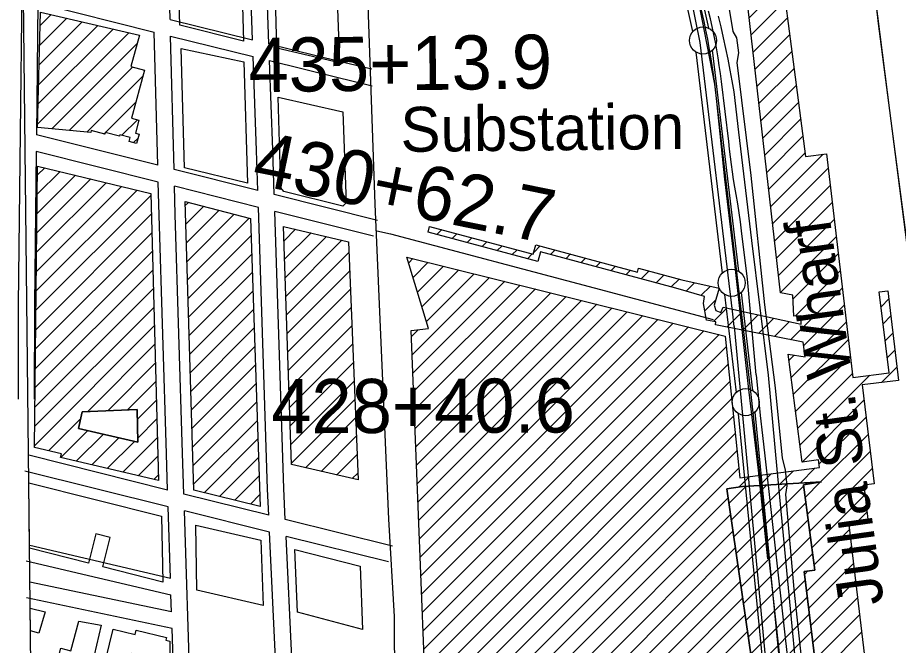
# Model space of a CAD drawing. Extents: x 3677843 to 3715951, y 511991 to 537744.
# Drawn here: x 3681974 to 3683602, y 526703 to 527864 of the extents above; entities that cross this region are included whole.
import ezdxf

# ---------------------------------------------------------------- set-up
doc = ezdxf.new("R2010")
doc.units = 0
for name, color, linetype in [('V-BLDG-IDEN', 7, 'Continuous'), ('V-BLDG-OTLN', 7, 'Continuous'), ('V-CHAN-DOCK', 7, 'Continuous'), ('V-FLOD-BASE', 7, 'Continuous'), ('V-GRID-FRAM', 7, 'Continuous'), ('V-RAIL-TRAK', 7, 'Continuous'), ('V-RIVR-EDGE', 7, 'Continuous'), ('V-RIVR-FERY', 7, 'Continuous'), ('V-ROAD-CNTR', 7, 'Continuous'), ('V-SITE-OTLN', 7, 'Continuous'), ('V-SITE-OTLN-IDEN', 7, 'Continuous'), ('V-SURV-IDEN', 7, 'Continuous'), ('V-SURV-LINE', 7, 'Continuous'), ('V-UTIL-LINE', 7, 'Continuous')]:
    doc.layers.add(name, color=color, linetype=linetype)

msp = doc.modelspace()

# ---------------------------------------------------------------- linework, layer by layer
at = {"layer": 'V-BLDG-OTLN'}
for p, q in [((3683326.4, 527863.3), (3683389.2, 527926.2)), ((3683330, 527831.6), (3683393.2, 527894.9)), ((3682015.7, 527848.9), (3682036.1, 527869.4)), ((3682013.6, 527776.1), (3682093.4, 527855.9)), ((3682014.6, 527812.5), (3682064.8, 527862.6)), ((3683333.6, 527799.8), (3683397.3, 527863.5)), ((3682011.5, 527703.4), (3682150.7, 527842.5)), ((3682012.6, 527739.7), (3682122, 527849.2)), ((3682010.5, 527667), (3682179.3, 527835.8)), ((3683337.2, 527768.1), (3683401.3, 527832.2)), ((3682037.1, 527658.2), (3682194.6, 527815.7)), ((3683340.8, 527736.3), (3683405.4, 527800.9)), ((3682069.4, 527655.2), (3682186.6, 527772.4)), ((3682101.8, 527652.2), (3682205.8, 527756.2)), ((3683344.4, 527704.6), (3683409.4, 527769.6)), ((3683348, 527672.8), (3683413.5, 527738.3)), ((3682136.3, 527651.4), (3682192.5, 527707.5)), ((3683351.6, 527641.1), (3683417.5, 527707)), ((3682166.4, 527646.1), (3682195.2, 527674.9)), ((3683355.2, 527609.3), (3683421.6, 527675.7)), ((3682133.5, 527648.6), (3682135.4, 527650.4)), ((3682188.2, 527632.5), (3682196.4, 527640.7)), ((3683358.8, 527577.6), (3683425.6, 527644.4)), ((3683362.4, 527545.8), (3683429.6, 527613.1)), ((3683366, 527514.1), (3683463, 527611)), ((3682010.2, 527537.1), (3682052.3, 527579.3)), ((3682010.6, 527572.9), (3682023.9, 527586.2)), ((3683369.7, 527482.3), (3683472.4, 527585.1)), ((3682009.4, 527465.6), (3682109.2, 527565.4)), ((3682009.8, 527501.4), (3682080.8, 527572.3)), ((3682008.2, 527358.4), (3682194.6, 527544.7)), ((3682008.6, 527394.1), (3682166.1, 527551.6)), ((3682009, 527429.9), (3682137.7, 527558.5)), ((3683373.3, 527450.6), (3683476.1, 527553.5)), ((3682007.8, 527322.6), (3682220.5, 527535.3)), ((3682283.9, 527516.1), (3682289.7, 527521.9)), ((3682284.9, 527481.8), (3682317.8, 527514.6)), ((3683376.9, 527418.9), (3683479.9, 527521.9)), ((3682007.4, 527286.8), (3682221.4, 527500.9)), ((3682286, 527447.4), (3682345.9, 527507.4)), ((3682287, 527413.1), (3682374, 527500.1)), ((3682288, 527378.8), (3682402.1, 527492.9)), ((3683380.5, 527387.1), (3683483.6, 527490.2)), ((3682007, 527251.1), (3682222.3, 527466.4)), ((3682466.4, 527451.1), (3682487.8, 527472.5)), ((3682467.5, 527416.9), (3682516.4, 527465.7)), ((3682749.1, 527462.9), (3682757.9, 527471.7)), ((3682777, 527455.4), (3682785.8, 527464.2)), ((3682289, 527344.4), (3682405.4, 527460.8)), ((3682468.7, 527382.6), (3682544.9, 527458.9)), ((3682469.8, 527348.4), (3682573.5, 527452.1)), ((3682804.9, 527447.9), (3682813.7, 527456.7)), ((3682832.8, 527440.4), (3682841.5, 527449.2)), ((3683384.1, 527355.4), (3683487.4, 527458.6)), ((3682006.6, 527215.3), (3682223.3, 527432)), ((3682470.9, 527314.2), (3682586.4, 527429.7)), ((3682860.6, 527432.9), (3682869.4, 527441.7)), ((3682888.5, 527425.5), (3682897.3, 527434.2)), ((3682928, 527429.6), (3682940, 527441.6)), ((3682959.3, 527425.5), (3682967.9, 527434.1)), ((3682290, 527310.1), (3682406.6, 527426.6)), ((3682696.9, 527410.6), (3682704.6, 527418.4)), ((3682916.4, 527418), (3682925.2, 527426.8)), ((3682987.2, 527418), (3682995.8, 527426.7)), ((3683015, 527410.6), (3683023.6, 527419.2)), ((3683407.7, 527343.6), (3683491.1, 527427)), ((3682006.2, 527179.6), (3682224.2, 527397.5)), ((3682705, 527383.4), (3682733, 527411.3)), ((3682713.2, 527356.2), (3682761.3, 527404.3)), ((3682721.3, 527329), (3682789.6, 527397.3)), ((3683042.9, 527403.1), (3683051.5, 527411.7)), ((3683070.8, 527395.6), (3683079.4, 527404.2)), ((3683098.6, 527388.1), (3683107.2, 527396.7)), ((3682291.1, 527275.8), (3682407.7, 527392.4)), ((3682472, 527280), (3682587.8, 527395.7)), ((3682703.2, 527240.2), (3682846.2, 527383.2)), ((3682729.5, 527301.8), (3682817.9, 527390.2)), ((3683126.5, 527380.6), (3683141, 527395.1)), ((3683154.4, 527373.1), (3683168.9, 527387.6)), ((3683182.3, 527365.7), (3683196.7, 527380.1)), ((3683411.2, 527311.8), (3683494.8, 527395.4)), ((3682704.6, 527206.2), (3682874.6, 527376.2)), ((3682705.9, 527172.2), (3682902.9, 527369.1)), ((3683209.8, 527357.8), (3683225.6, 527373.6)), ((3683237.2, 527349.9), (3683254.7, 527367.4)), ((3683403, 527268.2), (3683498.6, 527363.8)), ((3682005.8, 527143.8), (3682225.1, 527363.1)), ((3682292.1, 527241.4), (3682408.9, 527358.2)), ((3682473.2, 527245.7), (3682589.1, 527361.7)), ((3682707.3, 527138.2), (3682931.2, 527362.1)), ((3682708.6, 527104.1), (3682959.5, 527355.1)), ((3682710, 527070.1), (3682987.8, 527348)), ((3682711.3, 527036.1), (3683016.2, 527341)), ((3682712.6, 527002.1), (3683044.5, 527334)), ((3683244.6, 527321.9), (3683264.8, 527342.1)), ((3683427.1, 527257), (3683502.3, 527332.2)), ((3683570.2, 527329.3), (3683584.5, 527343.7)), ((3682005.4, 527108.1), (3682226, 527328.6)), ((3682293.1, 527207.1), (3682410.1, 527324)), ((3682474.3, 527211.5), (3682590.5, 527327.7)), ((3682714, 526968.1), (3683072.8, 527326.9)), ((3682715.3, 526934.1), (3683101.1, 527319.9)), ((3683260.2, 527302.2), (3683284.8, 527326.8)), ((3683284.8, 527291.4), (3683313.9, 527320.5)), ((3682716.7, 526900.1), (3683129.5, 527312.9)), ((3682718, 526866.1), (3683157.8, 527305.8)), ((3682719.3, 526832), (3683186.1, 527298.8)), ((3683314.4, 527285.6), (3683343, 527314.2)), ((3683343.9, 527279.8), (3683372.1, 527308)), ((3683373.5, 527274), (3683401.1, 527301.7)), ((3683403.9, 527198.4), (3683506, 527300.5)), ((3683574, 527297.8), (3683588.3, 527312.1)), ((3682005, 527072.3), (3682226.9, 527294.2)), ((3682294.1, 527172.8), (3682411.2, 527289.9)), ((3682475.4, 527177.3), (3682591.8, 527293.7)), ((3682701.9, 527274.2), (3682714.3, 527286.7)), ((3682720.7, 526798), (3683214.4, 527291.8)), ((3682722, 526764), (3683242.7, 527284.7)), ((3682723.4, 526730), (3683271.1, 527277.7)), ((3683408, 527167.1), (3683509.8, 527268.9)), ((3683577.8, 527266.2), (3683592.1, 527280.6)), ((3682103.7, 527135.6), (3682227.8, 527259.8)), ((3682295.1, 527138.4), (3682412.4, 527255.7)), ((3682476.5, 527143), (3682593.2, 527259.7)), ((3682724.7, 526696), (3683284.1, 527255.3)), ((3683399.9, 527229.7), (3683409.8, 527239.6)), ((3683412, 527135.8), (3683513.5, 527237.3)), ((3683581.6, 527234.7), (3683595.9, 527249)), ((3682140.4, 527137), (3682228.7, 527225.3)), ((3682296.2, 527104.1), (3682413.6, 527221.5)), ((3682477.7, 527108.8), (3682594.5, 527225.7)), ((3682726.1, 526662), (3683287.4, 527223.3)), ((3683571.3, 527189.1), (3683599.7, 527217.5)), ((3683416.1, 527104.5), (3683517.3, 527205.7)), ((3683420.1, 527073.2), (3683549.3, 527202.4)), ((3682177.2, 527138.4), (3682229.6, 527190.9)), ((3682297.2, 527069.8), (3682414.7, 527187.3)), ((3682478.8, 527074.6), (3682595.9, 527191.7)), ((3682727.4, 526628), (3683290.7, 527191.2)), ((3682195.3, 527121.2), (3682230.6, 527156.4)), ((3682298.2, 527035.4), (3682415.9, 527153.1)), ((3682479.9, 527040.3), (3682597.3, 527157.7)), ((3682728.7, 526593.9), (3683293.9, 527159.2)), ((3683424.2, 527042), (3683538.6, 527156.3)), ((3682030.9, 527062.8), (3682090.5, 527122.4)), ((3682195.8, 527086.3), (3682231.5, 527122)), ((3682506.3, 527031.4), (3682598.6, 527123.7)), ((3682730.1, 526559.9), (3683297.2, 527127.1)), ((3683455.5, 527037.9), (3683542.4, 527124.7)), ((3682299.2, 527001.1), (3682417.1, 527118.9)), ((3682053.6, 527050.2), (3682103.8, 527100.4)), ((3682082.2, 527043.4), (3682132.4, 527093.6)), ((3682168.1, 527023.3), (3682232.4, 527087.5)), ((3682535, 527024.7), (3682600, 527089.7)), ((3682731.4, 526525.9), (3683300.5, 527095)), ((3683458.5, 527005.5), (3683546.2, 527093.2)), ((3682110.9, 527036.7), (3682161, 527086.9)), ((3682139.5, 527030), (3682189.7, 527080.2)), ((3682318.7, 526985.3), (3682418.2, 527084.7)), ((3682563.7, 527018.1), (3682601.3, 527055.7)), ((3682732.8, 526491.9), (3683303.8, 527063)), ((3683434, 526945.7), (3683550, 527061.6)), ((3682196.8, 527016.6), (3682233.3, 527053.1)), ((3682347.2, 526978.3), (3682419.4, 527050.5)), ((3682734.1, 526457.9), (3683307.1, 527030.9)), ((3683383.3, 527001.1), (3683408.1, 527025.8)), ((3683420.9, 527003.3), (3683448.7, 527031.1)), ((3683438.3, 526914.6), (3683553.8, 527030.1)), ((3682225.4, 527009.9), (3682234.2, 527018.7)), ((3682375.6, 526971.4), (3682420.6, 527016.4)), ((3682592.4, 527011.4), (3682602.7, 527021.7)), ((3683307.6, 526996), (3683326.9, 527015.3)), ((3683345.7, 526998.8), (3683367.5, 527020.6)), ((3681995.8, 526883), (3681994.5, 527003.6)), ((3681994.5, 527003.6), (3682239.7, 526942.2)), ((3683288.8, 526965.4), (3683320.8, 526997.3)), ((3683293.3, 526934.5), (3683358.4, 526999.6)), ((3683297.8, 526903.7), (3683396, 527001.8)), ((3683302.3, 526872.8), (3683427, 526997.5)), ((3683429.8, 526976.8), (3683458.3, 527005.3)), ((3683430, 527000.5), (3683433.5, 527004)), ((3682404.1, 526964.5), (3682421.7, 526982.2)), ((3682735.4, 526423.9), (3683287.3, 526975.7)), ((3683442.5, 526883.4), (3683540.3, 526981.2)), ((3683306.8, 526842), (3683431.2, 526966.4)), ((3682239.7, 526942.2), (3682242.1, 526820.3)), ((3682736.8, 526389.9), (3683291.8, 526944.9)), ((3683521.9, 526927.5), (3683544.1, 526949.7)), ((3683311.3, 526811.1), (3683435.5, 526935.2)), ((3682118.5, 526909.5), (3682104.9, 526855.4)), ((3682144.9, 526902.8), (3682118.5, 526909.5)), ((3682738.1, 526355.8), (3683296.3, 526914)), ((3683446.7, 526852.3), (3683511.9, 526917.5)), ((3682131.1, 526848.4), (3682144.9, 526902.8)), ((3683315.8, 526780.3), (3683439.7, 526904.1)), ((3682104.9, 526855.4), (3681995.8, 526883)), ((3682739.5, 526321.8), (3683300.8, 526883.2)), ((3683432.4, 526802.7), (3683515.6, 526885.9)), ((3683320.3, 526749.4), (3683443.9, 526873)), ((3682242.1, 526820.3), (3682131.1, 526848.4)), ((3682740.8, 526287.8), (3683305.3, 526852.3)), ((3683436.3, 526771.2), (3683519.4, 526854.3)), ((3683428.5, 526834.1), (3683435.1, 526840.7)), ((3682742.2, 526253.8), (3683309.8, 526821.5)), ((3683324.8, 526718.6), (3683429.8, 526823.6)), ((3683440.2, 526739.7), (3683523.1, 526822.6)), ((3682743.5, 526219.8), (3683314.3, 526790.6)), ((3683329.4, 526687.7), (3683433.7, 526792.1)), ((3683444.1, 526708.2), (3683526.9, 526791)), ((3681997.5, 526730.3), (3681997, 526772)), ((3681997, 526772), (3682024.6, 526765.1)), ((3682024.6, 526765.1), (3682013.3, 526725.7)), ((3682747.5, 526188.5), (3683318.8, 526759.8)), ((3683333.9, 526656.9), (3683437.6, 526760.6)), ((3683448, 526676.8), (3683530.6, 526759.4)), ((3682013.3, 526725.7), (3681997.5, 526730.3)), ((3682751.9, 526157.5), (3683323.3, 526728.9)), ((3683338.4, 526626), (3683441.5, 526729.1)), ((3683451.8, 526645.3), (3683534.3, 526727.8))]:
    msp.add_line(p, q, dxfattribs=at)
for points in [[(3683449.9, 528826), (3683453.9, 528802.7), (3683451.5, 528802.3), (3683453.8, 528788.9), (3683395.5, 528778.9), (3683412.4, 528680), (3683422.1, 528681.7), (3683519.6, 528113), (3683407.9, 528093.9), (3683424.8, 527962.7), (3683385.1, 527957.6), (3683430.5, 527606.8), (3683469.2, 527611.8), (3683518.1, 527198.6)], [(3683247.8, 527304.6), (3683242.1, 527335.1), (3683243.7, 527348), (3683190.6, 527363.4), (3682940.5, 527430.6), (3682935.7, 527412.8), (3682732.6, 527467.3), (3682735.4, 527477.7), (3682927.1, 527426.2), (3682931.8, 527443.8), (3683119.9, 527393.3), (3683121.8, 527400.3), (3683202.1, 527378.7), (3683271.1, 527363.8), (3683261.8, 527332), (3683264.8, 527322.1), (3683273.9, 527318.3), (3683278.1, 527328.2), (3683422.6, 527297.1), (3683421.9, 527312.3), (3683409.1, 527311.7), (3683407.3, 527350.8), (3683384.1, 527354.9), (3683301.7, 528080.9)], [(3682864.7, 525370.9), (3682859.6, 525558.9), (3682831.8, 525560.2), (3682838, 525602.6), (3682804, 525621.8), (3682786.3, 525734.2), (3682829.8, 525788.6), (3682808.5, 525946.6), (3682779, 525968), (3682743.7, 526215.6), (3682701.5, 527285.2), (3682733.4, 527288.8), (3682693.7, 527421.1), (3683282.1, 527275), (3683308.9, 527013), (3683456.3, 527032), (3683454.5, 527045.9), (3683424.2, 527041.9), (3683398.3, 527241.5), (3683429.9, 527236.3), (3683426.2, 527263.7), (3683263.9, 527295.5), (3683265, 527301.2), (3683247.8, 527304.6)], [(3683518.1, 527198.6), (3683585, 527206.7), (3683566.9, 527356.6), (3683582.8, 527358.5), (3683602.7, 527192.8), (3683535.1, 527184.7), (3683557.2, 527001.7), (3683538.1, 526999.4), (3683546.3, 526931), (3683530.3, 526929.1), (3683530.3, 526928.5), (3683510.9, 526926.2), (3683572, 526409.1)]]:
    msp.add_lwpolyline(points, dxfattribs=at)
for points in [[(3682267.2, 528086.6), (3682384.7, 528059.3), (3682391.6, 527820.4), (3682273.9, 527850)], [(3682447, 528042.8), (3682560.4, 528014), (3682569.1, 527780.2), (3682452.9, 527807.2)], [(3682010.3, 527660.6), (3682016.4, 527874), (3682198.9, 527831.2), (3682183, 527773.3), (3682208.6, 527766.4), (3682184.4, 527677.8), (3682198.1, 527674.1), (3682191.6, 527650.2), (3682198.5, 527648.3), (3682193.7, 527631), (3682180.2, 527634.8), (3682182.1, 527641.8), (3682162.9, 527647.1), (3682162.2, 527644.3), (3682135.7, 527651.5), (3682134.8, 527648.2), (3682110.1, 527655), (3682109.1, 527651.5)], [(3682455.3, 527716.8), (3682575.1, 527689.5), (3682581.1, 527521.3), (3682574.9, 527514.9), (3682466.3, 527542.2), (3682460.7, 527549.2)], [(3682010.8, 527589.3), (3682220.4, 527538.4), (3682234.5, 527007.7), (3682053.2, 527050.3), (3682054.8, 527057.2), (3682005, 527068.9)], [(3682283.7, 527523.5), (3682404.3, 527492.3), (3682422.5, 526960), (3682299.6, 526989.9)], [(3682465.5, 527477.8), (3682585.6, 527449.2), (3682603.2, 527008.9), (3682480, 527037.5)], [(3682093.2, 527135.2), (3682086.6, 527104.4), (3682195.9, 527078.7), (3682195.1, 527139.1)], [(3682093.2, 527135.2), (3682195.1, 527139.1), (3682195.9, 527078.7), (3682086.6, 527104.4)], [(3683426.7, 526999.9), (3683448.1, 526842.5), (3683427.9, 526839.7), (3683461.5, 526566.8), (3683348.7, 526555.3), (3683284.8, 526992.8), (3683314.3, 526997), (3683460, 527005.6)], [(3683426.7, 526999.9), (3683460, 527005.6), (3683314.3, 526997), (3683284.8, 526992.8), (3683348.7, 526555.3), (3683461.5, 526566.8), (3683427.9, 526839.7), (3683448.1, 526842.5)], [(3682303.6, 526925.2), (3682423.2, 526897.9), (3682428.1, 526776.6), (3682305.4, 526805.5)], [(3682486.1, 526880.3), (3682607.3, 526849.8), (3682611.5, 526732.4), (3682491.1, 526764.5)], [(3682086.9, 526748.2), (3682128.5, 526740.5), (3682102.5, 526629.8), (3682060.3, 526639.6), (3682059.3, 526637.1), (3682039.4, 526642.4), (3682054, 526697.9), (3682072.5, 526693.1)], [(3682124, 526624.4), (3682150.4, 526733), (3682191, 526723.1), (3682193, 526731.2), (3682249.2, 526717.5), (3682248.1, 526712.9), (3682255.5, 526711.1), (3682254.9, 526664.8), (3682203.7, 526672.9), (3682203.8, 526684.7), (3682184.9, 526687.9), (3682167.2, 526614)]]:
    msp.add_lwpolyline(points, close=True, dxfattribs=at)
at = {"layer": 'V-CHAN-DOCK'}
for points in [[(3683375.1, 527179.1), (3683355.3, 527332.9), (3683329.8, 527571.8), (3683304.1, 527780.9), (3683307.2, 527798.8), (3683303.6, 527826.1), (3683296.9, 527837.9), (3683270.9, 527994.9), (3683285.9, 528006), (3683261.8, 528045.2), (3683244, 528072.6), (3683188.5, 528216.2), (3683176.5, 528244.3), (3683211.2, 528250.2), (3683175.4, 528504.4), (3683130.1, 528768.8), (3683103.7, 528946.4), (3683124.1, 528949.1), (3683075.3, 529363.1), (3683224.2, 529384.5), (3683221.1, 529409.5), (3683293.5, 529422.3)], [(3683649.9, 527197.9), (3683628.3, 527366.5), (3683586.2, 527691.9), (3683542.3, 528041.6), (3683481.8, 528398), (3683437.2, 528667), (3683492.3, 528676.4), (3683436.3, 529035.6), (3683411.4, 529057.3), (3683383.7, 529053.1), (3683337.4, 529401.6), (3683297.3, 529397.6), (3683293.5, 529422.3)], [(3683516.1, 525271.2), (3683512.2, 525431), (3683509.7, 525626.3), (3683510.5, 525869.6), (3683494.3, 526037.2), (3683471.9, 526246.7), (3683467.1, 526286.5), (3683463.4, 526346.5), (3683437.5, 526549), (3683409.8, 526806.9), (3683393.9, 526982.2), (3683396.5, 526997.9), (3683393.8, 527027.8), (3683387.8, 527049.4), (3683375.1, 527179.1)]]:
    msp.add_lwpolyline(points, dxfattribs=at)
at = {"layer": 'V-FLOD-BASE'}
msp.add_line((3683298.5, 527292.9), (3683295.4, 527321), dxfattribs=at)
for points in [[(3683295.4, 527321), (3683236, 527817.9), (3683202.6, 527982.2)], [(3683298.5, 527292.9), (3683367.5, 526557.3), (3683392.9, 526356.2), (3683414.1, 526296.9), (3683457.9, 525889), (3683464.9, 525781.1), (3683458.9, 525389.1)]]:
    msp.add_lwpolyline(points, dxfattribs=at)
at = {"layer": 'V-GRID-FRAM'}
msp.add_lwpolyline([(3681899.6, 535587.1), (3713561.2, 535950.9), (3713778.1, 517769.3), (3682100.6, 517405.3), (3681899.6, 535587.1)], dxfattribs=at)
at = {"layer": 'V-RAIL-TRAK'}
msp.add_line((3683361.9, 527202.9), (3683331.5, 527451.7), dxfattribs=at)
for points in [[(3683218.8, 527958.7), (3683242.4, 527856.7), (3683245.8, 527840.4), (3683249.1, 527824.1), (3683252.1, 527807.7), (3683254.9, 527791.3), (3683257.5, 527774.9), (3683259.9, 527758.4), (3683262.1, 527742), (3683264, 527725.4), (3683265.8, 527708.9), (3683280.6, 527564.8), (3683297.8, 527420.1), (3683325.2, 527176.1), (3683342.8, 527026.8), (3683360.5, 526863.3)], [(3683339.5, 527203), (3683323.2, 527380.2), (3683312.5, 527469.2), (3683310.3, 527486.1), (3683307.9, 527502.9), (3683305.3, 527519.7), (3683302.5, 527536.5), (3683299.9, 527550.4), (3683297.6, 527564.4), (3683295.4, 527578.3), (3683293.5, 527592.4), (3683291.8, 527606.4), (3683290.3, 527620.5), (3683289, 527634.6), (3683275, 527745.8), (3683273.2, 527760.4), (3683271.2, 527774.9), (3683269, 527789.4), (3683266.5, 527803.8), (3683263.9, 527818.2), (3683261.1, 527832.6), (3683258.1, 527847), (3683254.9, 527861.3), (3683251.5, 527875.5)], [(3683331.5, 527451.7), (3683307.1, 527652), (3683298.4, 527726.5), (3683294.9, 527746.6), (3683291.2, 527766.6), (3683287.3, 527786.6), (3683283.3, 527806.6), (3683279, 527826.5), (3683274.5, 527846.4), (3683269.8, 527866.3)], [(3683339.5, 527203), (3683343.1, 527165.6), (3683347, 527128.3), (3683351.1, 527091), (3683355.6, 527053.8), (3683399.9, 526657), (3683442.5, 526272.4), (3683443.3, 526261.2), (3683443.8, 526250), (3683444.2, 526238.8), (3683444.3, 526227.7), (3683444.3, 526216.5), (3683444, 526205.3), (3683443.6, 526194.1), (3683442.9, 526183), (3683442, 526171.8)], [(3683411.5, 526680.6), (3683394.9, 526854.7), (3683378.3, 527028.8), (3683361.9, 527202.9)]]:
    msp.add_lwpolyline(points, dxfattribs=at)
at = {"layer": 'V-RIVR-EDGE'}
msp.add_lwpolyline([(3683541.3, 528059.7), (3683565.2, 527852.5), (3683594.1, 527630.6), (3683620.6, 527429), (3683642.2, 527254.3), (3683665, 527072.2), (3683712.5, 526695.3), (3683749.8, 526417.6), (3683777.7, 526064)], dxfattribs=at)
at = {"layer": 'V-RIVR-FERY'}
msp.add_spline([(3683395.6, 529471.3), (3683521.9, 529210.1), (3683605.1, 528969.7), (3683680.8, 528445.2), (3683751.5, 527893.7), (3683927.9, 527005.7), (3684042.4, 526379.7), (3684112.2, 525834.6), (3684119.2, 525226.8), (3684092.5, 524348.2), (3684041.6, 523650.6), (3683951.4, 522948.6), (3683790.8, 522287.1), (3683653.8, 521935.8), (3683329.6, 521213.6), (3682839.7, 520457.3), (3682512.6, 519997.8), (3682286.2, 519636), (3682113.5, 519264), (3682089.8, 519186.3)], degree=3, dxfattribs=at)
at = {"layer": 'V-ROAD-CNTR'}
msp.add_line((3682637.7, 527469.3), (3682663.2, 527463.9), dxfattribs=at)
for points in [[(3682573.7, 528917.2), (3682614.7, 528079.4), (3682634, 527518.8), (3682659.5, 526936.6), (3682670, 526756.3)], [(3682004, 528580.6), (3681985.4, 528232.2), (3681974.9, 527333.4), (3681974.7, 527158.4)], [(3682255.7, 527860.4), (3682249.4, 528091.7), (3682248.9, 528109.3)], [(3682408.3, 527822.8), (3682399.3, 528071.6)], [(3682438.5, 527815.4), (3682429.6, 528064)], [(3682011.4, 527890.8), (3682008.6, 527646.9)], [(3682011.4, 527890.8), (3682226.3, 527836.8)], [(3682255.7, 527860.4), (3682408.3, 527822.8)], [(3682232.9, 527590.6), (3682226.3, 527836.8)], [(3682256.5, 527829.3), (3682409.4, 527791.7)], [(3682263.1, 527583), (3682256.5, 527829.3)], [(3682438.5, 527815.4), (3682568.6, 527783.4), (3682628.7, 527768.8)], [(3682418, 527544.1), (3682415.6, 527618), (3682409.4, 527791.7)], [(3682448.3, 527536.5), (3682445.6, 527619), (3682439.7, 527784.2)], [(3682439.7, 527784.2), (3682561.5, 527754.2), (3682629.6, 527737.7)], [(3682232.9, 527590.6), (3682008.6, 527646.9)], [(3682008.2, 527616), (3682004.9, 527333.2), (3682004.7, 527158.4)], [(3682233.7, 527559.4), (3682008.2, 527616)], [(3682418, 527544.1), (3682263.1, 527583)], [(3682251, 526990.4), (3682248.8, 527057.3), (3682235.4, 527498.7), (3682233.7, 527559.4)], [(3682419.1, 527512.9), (3682264, 527551.8)], [(3682281.2, 526982.9), (3682278.8, 527058.2), (3682265.4, 527499.5), (3682264, 527551.8)], [(3682639.2, 527488.6), (3682448.3, 527536.5)], [(3682438.3, 526943.6), (3682436.1, 526992.1), (3682419.1, 527512.9)], [(3682631.9, 527459.5), (3682449.3, 527505.3)], [(3682468.7, 526936), (3682466.1, 526993.3), (3682449.3, 527505.3)], [(3682663.2, 527463.9), (3683039.7, 527364.1), (3683259.7, 527305.7)], [(3682251, 526990.4), (3681994.7, 527054.5)], [(3682252, 526959.3), (3681987.4, 527025.4)], [(3682438.3, 526943.6), (3682281.2, 526982.9)], [(3682256.3, 526827.6), (3682252, 526959.3)], [(3682439.8, 526912.3), (3682282.2, 526951.7)], [(3682295.1, 526581.7), (3682293.1, 526620.2), (3682282.2, 526951.7)], [(3682666.9, 526886.5), (3682468.7, 526936)], [(3682450.7, 526678.7), (3682439.8, 526912.3)], [(3682659.6, 526857.4), (3682470.2, 526904.7)], [(3682480.7, 526680.1), (3682470.2, 526904.7)], [(3681996.3, 526888.6), (3682256.3, 526827.6)], [(3681989.4, 526859.4), (3682257.3, 526796.5)], [(3682258.3, 526765.4), (3681996.7, 526820.3)], [(3682258.3, 526765.4), (3682257.3, 526796.5)], [(3682259.3, 526734.5), (3681990.5, 526790.9)], [(3682264.7, 526589.1), (3682263.1, 526618.9), (3682259.3, 526734.5)]]:
    msp.add_lwpolyline(points, dxfattribs=at)
msp.add_arc((3689134.6, 526772.5), 6464.7, 180.14371, 184.06249, dxfattribs=at)
at = {"layer": 'V-SITE-OTLN'}
msp.add_lwpolyline([(3682392.2, 527782.1), (3682398.8, 527557.8), (3682282.2, 527586), (3682276.4, 527806.8)], close=True, dxfattribs=at)
at = {"layer": 'V-SURV-LINE'}
for points in [[(3683222, 527837.7), (3683196.2, 527954.8)], [(3683225.5, 527961.3), (3683251.3, 527844.2)], [(3683276.9, 527391.5), (3683228.5, 527799.8)], [(3683258.2, 527803.4), (3683306.7, 527395)], [(3683302.7, 527170.9), (3683281.5, 527351.8)], [(3683311.3, 527355.3), (3683332.5, 527174.4)], [(3683366, 526528.7), (3683306.9, 527131.5)], [(3683336.8, 527134.4), (3683395.9, 526531.6)]]:
    msp.add_lwpolyline(points, dxfattribs=at)
for centre in [(3683241, 527821.4), (3683294.1, 527373.4), (3683319.9, 527152.8)]:
    msp.add_circle(centre, 25, dxfattribs=at)
at = {"layer": 'V-UTIL-LINE'}
msp.add_lwpolyline([(3683452.9, 525954.1), (3683385, 526665.8), (3683329.3, 527172.7), (3683262.9, 527740.5), (3683239.6, 527861), (3683220.6, 527958.7), (3683159.3, 528188.6), (3683084.9, 528629.5), (3683030.1, 529029.4), (3683002.2, 529384.8), (3682932.6, 529730.4), (3682900, 530012.9), (3682876.8, 530381.3), (3682871.2, 530572.7), (3682906.5, 530843.5), (3682949.3, 531079.9), (3682986.4, 531237), (3683056.1, 531445.5), (3683116.5, 531551), (3683192.7, 531667.1), (3683295.8, 531795.3), (3683329.3, 531838.1)], dxfattribs=at)

# ---------------------------------------------------------------- texts
at = {"layer": 'V-BLDG-IDEN'}
msp.add_text('Julia St. Wharf', height=83, rotation=97.9893, dxfattribs=at).set_placement((3683575.7, 526781.3))
at = {"layer": 'V-SITE-OTLN-IDEN'}
msp.add_text('Substation', height=83, rotation=0.5827, dxfattribs=at).set_placement((3682682.1, 527615.4))
at = {"layer": 'V-SURV-IDEN'}
for s, rotation, p in [('   435+13.9  ', 0.7034, (3682289.7, 527724.4)), ('   430+62.7  ', 348.5449, (3682295.2, 527578.7)), ('   428+40.6  ', 0.1568, (3682331.4, 527094.9))]:
    msp.add_text(s, height=100, rotation=rotation, dxfattribs=at).set_placement(p)

doc.saveas('drawing.dxf')
